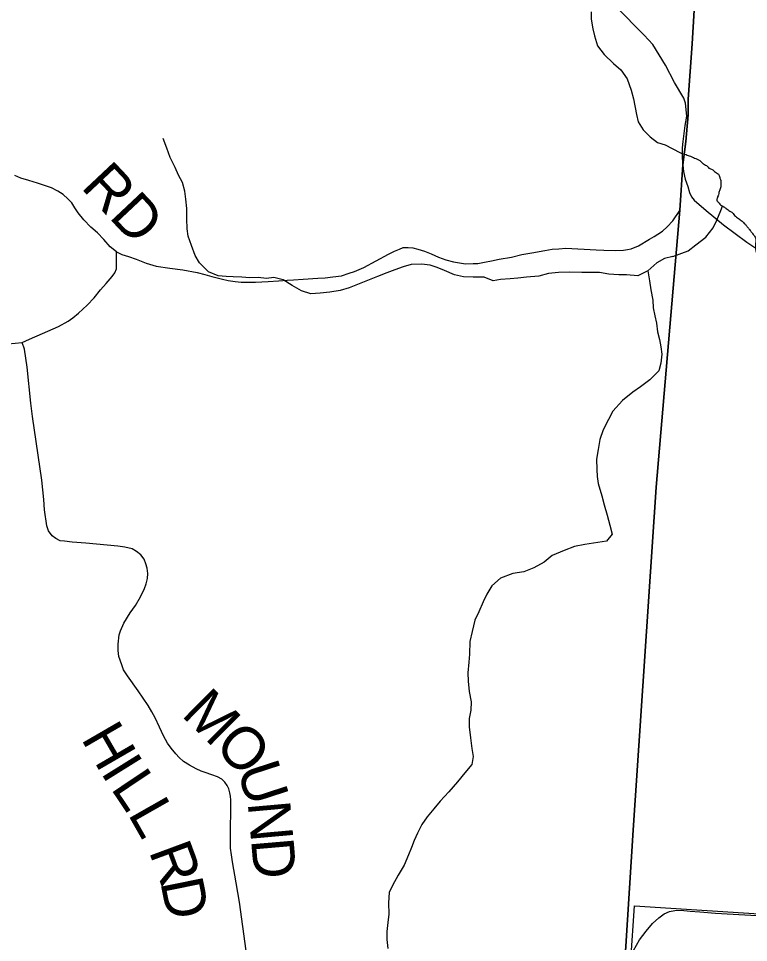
# Model space of a CAD drawing. Extents: x -13.7 to 34, y 0 to 32.3.
# Drawn here: x 24.863 to 25.84, y 15.995 to 17.233 of the extents above; entities that cross this region are included whole.
import ezdxf

# ---------------------------------------------------------------- set-up
doc = ezdxf.new("R2010")
doc.units = 0
for name, color, linetype in [('GM_X_Corporation', 7, 'Continuous'), ('GM_X_County_Road', 7, 'Continuous'), ('GM_X_County_Road_Text', 7, 'Continuous'), ('GM_X_Minor_River', 7, 'Continuous'), ('GM_X_State_Route', 7, 'Continuous'), ('GM_X_Township_Road', 7, 'Continuous')]:
    doc.layers.add(name, color=color, linetype=linetype)

msp = doc.modelspace()

# ---------------------------------------------------------------- linework, layer by layer
at = {"layer": 'GM_X_Corporation'}
for points in [[(29.9598, 20.9), (26.0026, 20.9), (25.9834, 20.5724), (25.9566, 20.1753), (25.9462, 20.0191), (25.9325, 19.8164), (25.917, 19.5276), (25.8969, 19.2407), (25.8969, 19.1723), (25.8715, 18.8281), (25.8521, 18.5644), (25.8512, 18.5523), (25.8396, 18.3951), (25.8286, 18.2247), (25.8036, 17.8534), (25.7648, 17.1991), (25.7595, 17.1252), (25.7591, 17.1039), (25.7561, 17.0683), (25.752, 17.037), (25.7481, 16.9763), (25.7164, 16.6052), (25.6857, 16.1459), (25.6733, 15.948)], [(29.9598, 20.9), (26.0026, 20.9), (25.9834, 20.5724), (25.9566, 20.1753), (25.9462, 20.0191), (25.9325, 19.8164), (25.917, 19.5276), (25.8969, 19.2407), (25.8969, 19.1723), (25.8715, 18.8281), (25.8521, 18.5644), (25.8512, 18.5523), (25.8396, 18.3951), (25.8286, 18.2247), (25.8036, 17.8534), (25.7648, 17.1991), (25.7595, 17.1252), (25.7591, 17.1039), (25.7561, 17.0683), (25.752, 17.037), (25.7481, 16.9763), (25.7164, 16.6052), (25.6857, 16.1459), (25.6733, 15.948)], [(25.6733, 15.948), (25.6857, 16.1459), (25.7164, 16.6052), (25.7481, 16.9763), (25.752, 17.037), (25.7561, 17.0683), (25.7591, 17.1039), (25.7595, 17.1252), (25.7648, 17.1991), (25.8036, 17.8534), (25.8286, 18.2247), (25.8396, 18.3951), (25.8512, 18.5523)], [(25.6733, 15.948), (25.6857, 16.1459), (25.7164, 16.6052), (25.7481, 16.9763), (25.752, 17.037), (25.7561, 17.0683), (25.7591, 17.1039), (25.7595, 17.1252), (25.7648, 17.1991), (25.8036, 17.8534), (25.8286, 18.2247), (25.8396, 18.3951), (25.8512, 18.5523)]]:
    msp.add_lwpolyline(points, dxfattribs=at)
msp.add_lwpolyline([(25.6876, 16.0444), (26.7165, 15.9781), (26.6464, 14.9606), (25.6185, 15.0191)], close=True, dxfattribs=at)
at = {"layer": 'GM_X_County_Road'}
for points in [[(24.9936, 16.9205), (24.9855, 16.9271), (24.9767, 16.9372), (24.9682, 16.9458), (24.9595, 16.9537), (24.95, 16.9634), (24.9425, 16.9729), (24.938, 16.9796), (24.9338, 16.986), (24.9285, 16.9917), (24.9225, 16.9975), (24.9154, 17.0019), (24.9067, 17.0061), (24.8974, 17.0095), (24.8881, 17.0126), (24.8766, 17.0159), (24.8657, 17.0191), (24.8576, 17.0226)], [(24.9936, 16.9205), (25.0007, 16.917), (25.0098, 16.9142), (25.0201, 16.9106), (25.0337, 16.9052), (25.0471, 16.9013), (25.0653, 16.8985), (25.0825, 16.8962), (25.1016, 16.8928), (25.1119, 16.8902), (25.1216, 16.8876), (25.1357, 16.884), (25.1432, 16.8823), (25.1527, 16.8807), (25.1607, 16.8799), (25.1671, 16.8797), (25.1797, 16.88), (25.197, 16.8809), (25.2108, 16.8818), (25.2225, 16.8827), (25.2307, 16.883), (25.2436, 16.884), (25.2636, 16.8853), (25.2734, 16.8859), (25.2836, 16.8871), (25.2949, 16.8886), (25.3052, 16.8918), (25.3125, 16.894), (25.325, 16.8997), (25.358, 16.9174), (25.3659, 16.9213), (25.3728, 16.9242), (25.3777, 16.9262), (25.3842, 16.9262), (25.3906, 16.9257), (25.3971, 16.9241), (25.4061, 16.9214), (25.4151, 16.9177), (25.4248, 16.9134), (25.4348, 16.91), (25.4449, 16.9072), (25.4533, 16.9057), (25.461, 16.9044), (25.4714, 16.9048), (25.4775, 16.905), (25.4865, 16.9067), (25.4958, 16.9084), (25.5061, 16.9106), (25.5228, 16.9136), (25.5364, 16.9169), (25.55, 16.9192), (25.5673, 16.9221), (25.577, 16.9239), (25.5863, 16.9247), (25.5953, 16.9254), (25.6359, 16.9234), (25.6462, 16.9228), (25.6616, 16.9224), (25.6725, 16.9226), (25.6779, 16.9237), (25.683, 16.9247), (25.6927, 16.9287), (25.7075, 16.9376), (25.7138, 16.9412), (25.7188, 16.944), (25.7248, 16.9482), (25.7311, 16.9538), (25.7388, 16.962), (25.7483, 16.9758)], [(24.8676, 16.799), (24.8771, 16.8035), (24.8945, 16.8112), (24.9159, 16.8206), (24.9291, 16.8277), (24.9353, 16.832), (24.9431, 16.8382), (24.9545, 16.849), (24.9638, 16.8589), (24.9722, 16.8696), (24.9799, 16.8781), (24.9879, 16.8876), (24.9917, 16.8923), (24.9936, 16.8976), (24.9936, 16.9036), (24.9936, 16.912), (24.9936, 16.9205)], [(24.8485, 16.7975), (24.8676, 16.799)], [(25.1672, 15.9843), (25.1584, 16.0491), (25.154, 16.0751), (25.1492, 16.1033), (25.1476, 16.1129), (25.1466, 16.1218), (25.1463, 16.1432), (25.1469, 16.1759), (25.1468, 16.1861), (25.1465, 16.1915), (25.1456, 16.1957), (25.1443, 16.2011), (25.1419, 16.2054), (25.1388, 16.21), (25.1347, 16.2139), (25.1291, 16.217), (25.1214, 16.2201), (25.1127, 16.2231), (25.1073, 16.225), (25.1005, 16.228), (25.0915, 16.2327), (25.0836, 16.2378), (25.0779, 16.2429), (25.0731, 16.2479), (25.0668, 16.2556), (25.0622, 16.2625), (25.0569, 16.2721), (25.0515, 16.2839), (25.0457, 16.2964), (25.0412, 16.3045), (25.036, 16.3126), (25.0227, 16.3322), (25.0087, 16.3527), (25.0033, 16.3607), (25.0008, 16.3672), (24.9971, 16.3785), (24.9962, 16.3865), (24.9961, 16.3949), (24.9972, 16.4073), (24.9992, 16.413), (25.0038, 16.4232), (25.0119, 16.4368), (25.0193, 16.4466), (25.026, 16.4584), (25.0314, 16.4697), (25.0337, 16.4759), (25.0353, 16.4827), (25.0358, 16.4896), (25.035, 16.4967), (25.0332, 16.5025), (25.0308, 16.5088), (25.0263, 16.5147), (25.0206, 16.5192), (25.0147, 16.5225), (25.0049, 16.5248), (24.9956, 16.5263), (24.9527, 16.5304), (24.9345, 16.5317), (24.9241, 16.5327), (24.9182, 16.5335), (24.9125, 16.5364), (24.9077, 16.5402), (24.9028, 16.5466), (24.9005, 16.5536), (24.8974, 16.5747), (24.8966, 16.5886), (24.8936, 16.6145), (24.8812, 16.7001), (24.8792, 16.7179), (24.874, 16.7658), (24.8707, 16.79), (24.8676, 16.799)]]:
    msp.add_lwpolyline(points, dxfattribs=at)
at = {"layer": 'GM_X_Minor_River'}
for points in [[(25.6295, 17.2419), (25.6295, 17.2321), (25.6318, 17.2195), (25.6337, 17.2101), (25.6379, 17.1964), (25.6466, 17.1847), (25.6591, 17.1729), (25.669, 17.1642), (25.6777, 17.1525), (25.683, 17.1369), (25.6861, 17.1256), (25.6899, 17.1043), (25.6922, 17.0945), (25.699, 17.0839), (25.7085, 17.0744), (25.7183, 17.0672), (25.7286, 17.0638), (25.7482, 17.0535)], [(25.7386, 16.9142), (25.7276, 16.9117), (25.7174, 16.906), (25.7053, 16.895), (25.6917, 16.8882), (25.6765, 16.8897), (25.6663, 16.8897), (25.653, 16.8908), (25.6405, 16.893), (25.6167, 16.893), (25.6, 16.8934), (25.5856, 16.893), (25.5724, 16.8914), (25.5595, 16.888), (25.5428, 16.8865), (25.5311, 16.8853), (25.5208, 16.8842), (25.508, 16.8834), (25.4981, 16.8818), (25.486, 16.8864), (25.4716, 16.8867), (25.4583, 16.8871), (25.4462, 16.8897), (25.433, 16.8954), (25.4231, 16.8996), (25.4136, 16.9026), (25.4023, 16.9041), (25.3882, 16.9037), (25.3776, 16.9003), (25.3667, 16.8965), (25.3557, 16.8923), (25.3432, 16.8873), (25.3167, 16.8767), (25.3053, 16.8725), (25.2932, 16.8687), (25.2796, 16.8664), (25.2663, 16.8652), (25.2538, 16.8644), (25.2413, 16.8682), (25.2292, 16.8754), (25.2171, 16.883), (25.2046, 16.886), (25.1947, 16.8848), (25.1833, 16.886), (25.1724, 16.8856), (25.1614, 16.8867), (25.15, 16.8871), (25.1405, 16.8874), (25.1299, 16.8885), (25.117, 16.8938), (25.1049, 16.9059), (25.0992, 16.9154), (25.0943, 16.9291), (25.0897, 16.9416), (25.0886, 16.9514), (25.0878, 16.9647), (25.0878, 16.9784), (25.0866, 16.9913), (25.0851, 17.0019), (25.082, 17.0136), (25.0767, 17.0231), (25.0722, 17.0337), (25.0657, 17.047), (25.0612, 17.0595), (25.0562, 17.0724)], [(25.7386, 16.9142), (25.7593, 16.9217), (25.7695, 16.9297), (25.7828, 16.94), (25.7926, 16.9529), (25.7975, 16.9628), (25.8032, 16.9757), (25.8052, 16.9818)], [(25.7051, 16.8949), (25.7076, 16.8818), (25.7091, 16.8696), (25.7118, 16.8556), (25.7126, 16.8457), (25.7148, 16.8347), (25.7171, 16.8249), (25.7183, 16.8135), (25.7209, 16.8033), (25.7229, 16.7934), (25.724, 16.7836), (25.7229, 16.7714), (25.7199, 16.7612), (25.7078, 16.749), (25.6953, 16.7395), (25.6854, 16.7327), (25.6714, 16.7213), (25.6586, 16.7069), (25.6525, 16.6959), (25.6453, 16.6822), (25.6412, 16.6689), (25.6389, 16.6556), (25.6367, 16.6427), (25.6371, 16.6291), (25.6375, 16.6196), (25.639, 16.6101), (25.6436, 16.5938), (25.647, 16.5817), (25.6508, 16.5677), (25.6542, 16.5544), (25.6576, 16.5423), (25.6501, 16.5328), (25.6209, 16.5286), (25.6069, 16.5259), (25.5933, 16.5202), (25.577, 16.5137), (25.5664, 16.505), (25.5528, 16.4974), (25.5391, 16.4917), (25.5244, 16.4898), (25.5081, 16.4833), (25.4964, 16.473), (25.4899, 16.462), (25.485, 16.4518), (25.479, 16.4381), (25.4737, 16.4271), (25.4699, 16.4119), (25.4669, 16.3983), (25.4665, 16.3816), (25.4654, 16.3706), (25.4643, 16.3566), (25.4647, 16.3452), (25.4662, 16.3315), (25.4685, 16.3175), (25.4682, 16.3065), (25.4659, 16.2955), (25.4659, 16.2841), (25.4678, 16.2693), (25.4694, 16.2553), (25.4716, 16.2443), (25.4694, 16.2337), (25.4603, 16.2227), (25.4505, 16.2105), (25.4387, 16.1969), (25.427, 16.1847), (25.4187, 16.1745), (25.41, 16.1635), (25.4028, 16.1532), (25.3968, 16.1418), (25.3926, 16.132), (25.3888, 16.1225), (25.3847, 16.1126), (25.379, 16.0989), (25.3711, 16.0853), (25.3635, 16.0716), (25.359, 16.0621), (25.3582, 16.0485), (25.3583, 16.0333), (25.3571, 16.0219), (25.3556, 16.0102), (25.3557, 15.9992), (25.3572, 15.9874)]]:
    msp.add_lwpolyline(points, dxfattribs=at)
msp.add_spline([(25.7482, 17.0535), (25.7517, 17.0522), (25.7547, 17.0513), (25.7581, 17.0501), (25.7607, 17.0492), (25.7641, 17.048), (25.7663, 17.0468), (25.7697, 17.0455), (25.7764, 17.0415), (25.7797, 17.0383), (25.7827, 17.0367), (25.7849, 17.0351), (25.7871, 17.0328), (25.7916, 17.0307), (25.7946, 17.0283), (25.7998, 17.0244), (25.8012, 17.0213), (25.8019, 17.019), (25.8029, 17.0163), (25.8032, 17.0121), (25.803, 17.0076), (25.8013, 17.0023), (25.8005, 17), (25.8, 16.997), (25.7988, 16.9944), (25.7983, 16.9921), (25.7975, 16.9899), (25.8, 16.9867), (25.8015, 16.9844), (25.8041, 16.9824), (25.807, 16.9808), (25.8104, 16.9784), (25.8152, 16.9752), (25.8186, 16.9728), (25.8204, 16.9705), (25.8252, 16.9662), (25.8304, 16.9626), (25.8344, 16.9586), (25.837, 16.9559), (25.8399, 16.9524), (25.8432, 16.9481), (25.8454, 16.9453), (25.8475, 16.9426), (25.8497, 16.938), (25.85, 16.9353), (25.8499, 16.933), (25.8494, 16.9308), (25.8493, 16.9277), (25.8496, 16.9247), (25.8499, 16.922), (25.8506, 16.9193), (25.8509, 16.917), (25.8516, 16.9147), (25.8522, 16.9117), (25.8525, 16.9094), (25.8536, 16.9063), (25.8542, 16.9033), (25.857, 16.8971), (25.8581, 16.8944), (25.8603, 16.8913), (25.8621, 16.8886), (25.8647, 16.8862), (25.8695, 16.8838), (25.8718, 16.8829), (25.874, 16.8825), (25.877, 16.8812), (25.8793, 16.8804), (25.8895, 16.8789), (25.8936, 16.8788), (25.8974, 16.8783), (25.9012, 16.8785), (25.9073, 16.8783), (25.9096, 16.8786), (25.9152, 16.8781), (25.9179, 16.8772), (25.9205, 16.8767), (25.9239, 16.8759), (25.9262, 16.875), (25.9303, 16.873), (25.9351, 16.8709), (25.9374, 16.8693), (25.9407, 16.8673), (25.9433, 16.8661), (25.9467, 16.8641), (25.9489, 16.8629), (25.9511, 16.8613), (25.9534, 16.8605), (25.9586, 16.858), (25.9639, 16.8559), (25.9676, 16.8543), (25.9736, 16.851), (25.9758, 16.8502), (25.9799, 16.8482), (25.9826, 16.8473), (25.9856, 16.8461), (25.9882, 16.8449), (25.9912, 16.8436)], degree=3, dxfattribs=at)
at = {"layer": 'GM_X_State_Route'}
msp.add_lwpolyline([(25.6859, 15.9845), (25.6942, 15.9987), (25.7032, 16.0106), (25.7117, 16.0205), (25.7198, 16.0281), (25.727, 16.0337), (25.7342, 16.0367), (25.7414, 16.0382), (25.7497, 16.0387), (25.762, 16.0373), (25.7748, 16.0364), (25.7959, 16.0346), (25.835, 16.0324), (25.8757, 16.0299)], dxfattribs=at)
at = {"layer": 'GM_X_Township_Road'}
for points in [[(25.7522, 17.0365), (25.7516, 17.0511), (25.7515, 17.06), (25.7525, 17.0684), (25.7551, 17.0898), (25.7573, 17.1025), (25.7559, 17.1196), (25.7536, 17.1263), (25.7409, 17.1474), (25.729, 17.1704), (25.7122, 17.1982), (25.7002, 17.2107), (25.6628, 17.2489)], [(25.7522, 17.0365), (25.7531, 17.0281), (25.7554, 17.0181), (25.7588, 17.0079), (25.761, 17.0002), (25.7637, 16.9942), (25.7672, 16.9896), (25.7834, 16.9759), (25.8068, 16.9569), (25.8379, 16.9333), (25.8486, 16.9265)]]:
    msp.add_lwpolyline(points, dxfattribs=at)

# ---------------------------------------------------------------- texts
at = {"layer": 'GM_X_County_Road_Text'}
for s, height, rotation, p in [('RD', 0.05682, 313.2412, (24.9449, 17.0068)), ('M', 0.0568, 315.3216, (25.0793, 16.2999)), ('H', 0.0568, 300.091, (24.9456, 16.2686)), ('O', 0.0568, 314.7321, (25.123, 16.2567)), ('I', 0.0568, 301.9123, (24.9717, 16.2236)), ('U', 0.0568, 288.0214, (25.1546, 16.2271)), ('L', 0.0568, 303.884, (24.9852, 16.2021)), ('L', 0.0568, 299.6311, (25.0083, 16.1677)), ('N', 0.0568, 275.1067, (25.1694, 16.1828)), ('R', 0.0568, 290.3546, (25.0367, 16.1177)), ('D', 0.0568, 274.8946, (25.1739, 16.1331)), ('D', 0.0568, 281.4635, (25.0523, 16.0762))]:
    msp.add_text(s, height=height, rotation=rotation, dxfattribs=at).set_placement(p)

doc.saveas('drawing.dxf')
